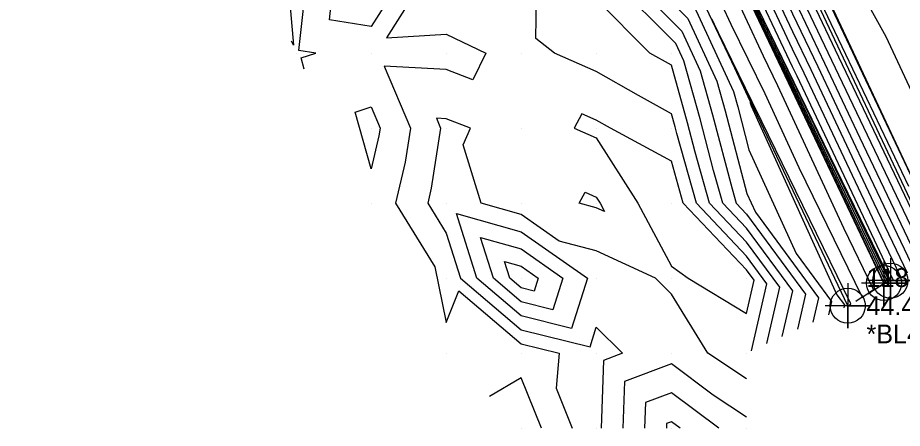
# Model space of a CAD drawing. Extents: x 2090860 to 2091277, y 159470 to 160080.
# Drawn here: x 2091052.9 to 2091170.8, y 159470 to 159524.7 of the extents above; entities that cross this region are included whole.
import ezdxf

# ---------------------------------------------------------------- set-up
doc = ezdxf.new("R2010")
doc.units = 0
for name, color, linetype in [('DTM Contours Major', 7, 'Continuous'), ('DTM Contours Minor', 7, 'Continuous'), ('Exist DTM Breakline', 7, 'Continuous'), ('Exist DTM Breakline Cogo Comment', 7, 'Continuous'), ('Exist DTM Breakline Cogo Elevation', 7, 'Continuous'), ('Exist DTM Breakline Cogo Number', 7, 'Continuous'), ('Exist DTM Breakline Cogo Point CELL', 7, 'Continuous'), ('Exist DTM QL2 LIDAR Elevation Point', 7, 'Continuous'), ('Exist Roads EOP', 7, 'Continuous')]:
    doc.layers.add(name, color=color, linetype=linetype)

msp = doc.modelspace()

# ---------------------------------------------------------------- linework, layer by layer
at = {"layer": 'DTM Contours Major'}
for points in [[(2091123.21, 159594.52), (2091129.91, 159580.68), (2091136.47, 159567.62), (2091138.12, 159564.05), (2091140.2, 159559.58), (2091146.27, 159546.39), (2091152.79, 159532.35), (2091156.16, 159525.23), (2091159.5, 159518.23), (2091166.04, 159504.37), (2091172.36, 159491.13)], [(2091128.34, 159593.56), (2091139.93, 159569.54), (2091140.97, 159567.34), (2091143.92, 159560.98), (2091147.21, 159553.98), (2091156.59, 159533.79), (2091161.27, 159523.96), (2091163.21, 159519.86), (2091171.58, 159502.29)], [(2091107.49, 159593.3), (2091109.23, 159589.68), (2091112.12, 159585.33), (2091119.2, 159570.67), (2091114.92, 159567.89), (2091120.85, 159560.32), (2091121.4, 159559.35), (2091126.5, 159553), (2091130.34, 159546.45), (2091137.49, 159533.43), (2091138.02, 159528.79), (2091142.19, 159524.62), (2091146.07, 159516.26), (2091147.17, 159512.31), (2091150.06, 159501.29), (2091151.2, 159498.79), (2091159.61, 159487.39), (2091158.87, 159484.16)], [(2091119.62, 159592.62), (2091130.86, 159569.9), (2091132.95, 159565.75), (2091135.92, 159559.3), (2091136.42, 159558.22), (2091136.43, 159558.2), (2091136.46, 159558.15), (2091149.11, 159531.02), (2091149.46, 159530.28), (2091156.03, 159516.65), (2091157.29, 159514), (2091169.04, 159489.62), (2091168.66, 159489.37)], [(2091165.38, 159487.43), (2091166.95, 159488.49), (2091162.97, 159496.65), (2091154.19, 159515.65), (2091152.26, 159519.58), (2091147.4, 159530.11), (2091145.52, 159535.03), (2091136.24, 159557.07), (2091135.82, 159557.96), (2091132.52, 159565.03), (2091132.34, 159565.41), (2091129.86, 159570.34), (2091117.8, 159591.64)], [(2091091.07, 159517.86), (2091090.65, 159519.35), (2091092.62, 159520), (2091090.36, 159520.36), (2091091.43, 159530), (2091090, 159532.48), (2091088.61, 159532.78), (2091089.65, 159521.06), (2091089.36, 159521.61)], [(2091107.07, 159530), (2091102.04, 159522.04), (2091110, 159522.53), (2091115.27, 159520), (2091113.55, 159516.45), (2091110, 159517.81), (2091101.75, 159518.25), (2091105.22, 159510), (2091104.52, 159505.48), (2091103.23, 159500), (2091108.46, 159491.54), (2091110, 159484.12), (2091111.68, 159488.32), (2091120, 159481.26), (2091125.06, 159480), (2091124.64, 159475.36), (2091126.8, 159470)], [(2091150.68, 159480.32), (2091152.74, 159489.26), (2091150, 159492.96), (2091143.34, 159500), (2091140.72, 159509.28), (2091140.49, 159510.16), (2091140, 159511.9), (2091135.63, 159514.37), (2091130, 159517.55), (2091124.42, 159520), (2091121.95, 159521.95), (2091122.09, 159530)], [(2091127.71, 159500), (2091128.53, 159501.47), (2091130, 159500.82), (2091130.52, 159500), (2091131.11, 159498.89), (2091130, 159499.4), (2091127.71, 159500)], [(2091120, 159488.71), (2091118.48, 159490), (2091117.78, 159492.22), (2091120, 159491.6), (2091122.27, 159490), (2091121.72, 159488.28), (2091120, 159488.71)], [(2091141.17, 159470), (2091140, 159470.88), (2091139.36, 159470.64), (2091139.34, 159470)]]:
    msp.add_lwpolyline(points, dxfattribs=at)
at = {"layer": 'DTM Contours Minor'}
for points in [[(2091131.42, 159598.52), (2091140.27, 159579.96), (2091144.16, 159571.35), (2091147, 159565.67), (2091150.37, 159558.45), (2091159.04, 159541.04), (2091163.85, 159530.74), (2091168.57, 159522.2), (2091174.47, 159509.57)], [(2091127.82, 159597.21), (2091138.56, 159574.44), (2091140.64, 159570.11), (2091144.22, 159562.5), (2091144.73, 159561.4), (2091156.04, 159537.32), (2091157.47, 159534.24), (2091158.19, 159532.74), (2091164.14, 159520.13), (2091165.09, 159518.14), (2091176.96, 159492.99)], [(2091126.02, 159596), (2091138.04, 159571.18), (2091139.12, 159569.03), (2091139.39, 159568.44), (2091143.03, 159560.61), (2091144.03, 159558.44), (2091155.66, 159533.4), (2091156.21, 159532.23), (2091162.28, 159519.5), (2091163.24, 159517.46), (2091175.19, 159492.42)], [(2091124.14, 159595.01), (2091132.62, 159577.51), (2091137.36, 159568.09), (2091138.54, 159565.51), (2091141.14, 159559.92), (2091145.52, 159550.4), (2091153.75, 159532.7), (2091156.17, 159527.57), (2091160.42, 159518.66), (2091165.11, 159508.73), (2091173.3, 159491.56)], [(2091125.08, 159595.51), (2091135.33, 159574.35), (2091138.24, 159568.56), (2091138.97, 159566.98), (2091142.08, 159560.26), (2091144.77, 159554.42), (2091154.7, 159533.05), (2091156.19, 159529.9), (2091161.35, 159519.08), (2091164.18, 159513.1), (2091174.25, 159491.99)], [(2091108.66, 159593.82), (2091110.67, 159589.63), (2091112.65, 159586.66), (2091121.5, 159568.34), (2091118.46, 159566.36), (2091122.67, 159560.99), (2091124.41, 159557.95), (2091127.88, 159553.64), (2091130.49, 159549.18), (2091140.66, 159530.65), (2091140.93, 159528.36), (2091142.99, 159526.29), (2091148.27, 159514.9), (2091148.85, 159512.85), (2091150.34, 159507.13), (2091156.63, 159493.3), (2091161.33, 159486.92), (2091160.92, 159485.12)], [(2091121.34, 159593.53), (2091124.5, 159587.01), (2091134.71, 159566.68), (2091137.27, 159561.12), (2091138.31, 159558.89), (2091147.77, 159538.35), (2091150.88, 159531.66), (2091156.12, 159520.56), (2091157.64, 159517.38), (2091167.91, 159495.64), (2091170.47, 159490.27), (2091170.45, 159490.22)], [(2091122.27, 159594.02), (2091127.2, 159583.84), (2091135.59, 159567.15), (2091137.7, 159562.59), (2091139.25, 159559.23), (2091147.02, 159542.37), (2091151.83, 159532.01), (2091156.14, 159522.9), (2091158.57, 159517.81), (2091166.98, 159500), (2091171.42, 159490.7)], [(2091106.31, 159592.78), (2091107.78, 159589.73), (2091111.59, 159584), (2091116.9, 159573), (2091111.38, 159569.41), (2091114.22, 159565.78), (2091116.48, 159560), (2091120, 159558.75), (2091125.12, 159552.37), (2091130.2, 159543.71), (2091134.31, 159536.22), (2091135.12, 159529.23), (2091141.39, 159522.94), (2091143.86, 159517.62), (2091145.5, 159511.77), (2091148.09, 159501.91), (2091148.63, 159500), (2091150, 159498.55), (2091157.89, 159487.86), (2091156.82, 159483.2)], [(2091119.2, 159592.39), (2091123.93, 159582.84), (2091132.63, 159565.57), (2091134.47, 159561.63), (2091136.12, 159558.08), (2091143.73, 159541.81), (2091148.81, 159530.9), (2091153.14, 159521.79), (2091155.67, 159516.52), (2091164.42, 159498.08), (2091168.58, 159489.45), (2091167.02, 159488.4)], [(2091119.41, 159592.5), (2091128.51, 159574.11), (2091132.78, 159565.65), (2091135.45, 159559.92), (2091136.28, 159558.14), (2091140.09, 159549.98), (2091148.96, 159530.96), (2091151.3, 159526.03), (2091155.85, 159516.59), (2091160.85, 159506.04), (2091168.81, 159489.54), (2091167.84, 159488.89)], [(2091120.4, 159593.03), (2091121.79, 159590.17), (2091133.83, 159566.21), (2091136.85, 159559.66), (2091137.37, 159558.55), (2091148.52, 159534.34), (2091149.92, 159531.31), (2091156.11, 159518.23), (2091156.71, 159516.96), (2091168.84, 159491.27), (2091169.53, 159489.84), (2091169.52, 159489.83)], [(2091164.56, 159486.95), (2091165.44, 159487.54), (2091157.04, 159504.73), (2091152.48, 159514.58), (2091147.96, 159523.81), (2091145.56, 159529.01), (2091140.8, 159541.42), (2091134.23, 159557.02), (2091133.33, 159559.3), (2091131.04, 159564.72), (2091127.32, 159571.89), (2091116.53, 159590.97)], [(2091166.2, 159487.92), (2091168.35, 159489.36), (2091167.98, 159490.11), (2091155.5, 159516.46), (2091154.97, 159517.54), (2091148.66, 159530.85), (2091147.36, 159533.64), (2091135.97, 159558.02), (2091133.49, 159563.33), (2091132.49, 159565.49), (2091119.34, 159591.57)], [(2091104.09, 159530), (2091100, 159523.53), (2091094.43, 159524.43), (2091095.04, 159530)], [(2091154.78, 159482.24), (2091156.17, 159488.32), (2091150, 159496.69), (2091146.87, 159500), (2091145.63, 159504.37), (2091143.83, 159511.24), (2091141.66, 159518.98), (2091140.6, 159521.26), (2091132.22, 159529.67)], [(2091152.73, 159481.28), (2091154.46, 159488.79), (2091150, 159494.82), (2091145.1, 159500), (2091143.18, 159506.82), (2091142.16, 159510.7), (2091140, 159518.39), (2091137.15, 159520), (2091130, 159527.24)], [(2091163.73, 159486.46), (2091163.92, 159486.59), (2091151.11, 159512.81), (2091150.78, 159513.52), (2091145.39, 159524.51), (2091150.48, 159513.54), (2091150.52, 159513.39), (2091150.62, 159512.98), (2091162.06, 159487.8), (2091163.05, 159486.46), (2091162.97, 159486.07)], [(2091100, 159504.59), (2091097.87, 159512.13), (2091100, 159512.83), (2091101.19, 159510), (2091101.03, 159508.97), (2091100, 159504.59)], [(2091150, 159476.59), (2091144.88, 159480), (2091140, 159487.89), (2091137.89, 159490), (2091130, 159493.66), (2091125.05, 159494.95), (2091120, 159498.5), (2091114.67, 159500), (2091112.24, 159507.76), (2091113.23, 159510), (2091110, 159511.24), (2091108.69, 159511.31), (2091109.24, 159510), (2091108.01, 159501.99), (2091107.54, 159500), (2091110, 159496.02), (2091111.89, 159490), (2091120, 159483.12), (2091129.16, 159480.84), (2091130, 159483.47), (2091133.47, 159480), (2091130.95, 159479.05), (2091130.63, 159470)], [(2091151.02, 159489.72), (2091150, 159491.1), (2091141.58, 159500), (2091140, 159505.6), (2091131.9, 159510), (2091130, 159511.07), (2091128.09, 159511.91), (2091127.04, 159510), (2091130, 159508.7), (2091135.51, 159500), (2091140, 159491.59), (2091142.23, 159490), (2091150, 159485.31), (2091151.02, 159489.72)], [(2091120, 159484.99), (2091114.09, 159490), (2091111.37, 159498.63), (2091120, 159496.2), (2091128.81, 159490), (2091126.68, 159483.32), (2091120, 159484.99)], [(2091120, 159486.85), (2091116.28, 159490), (2091114.57, 159495.43), (2091120, 159493.9), (2091125.54, 159490), (2091124.2, 159485.8), (2091120, 159486.85)], [(2091150, 159471.48), (2091145.58, 159474.42), (2091140, 159478.59), (2091133.75, 159476.25), (2091133.53, 159470)], [(2091122.71, 159470), (2091120, 159476.74), (2091115.77, 159474.23)], [(2091146.33, 159470), (2091140, 159474.73), (2091136.56, 159473.44), (2091136.44, 159470)]]:
    msp.add_lwpolyline(points, dxfattribs=at)
at = {"layer": 'Exist DTM Breakline'}
for points in [[(2091168.33, 159489.35), (2091148.61, 159530.83), (2091132.31, 159565.39), (2091116.34, 159597.57), (2091098.7, 159637.59), (2091084.7, 159667.25), (2091067.16, 159699.24), (2091053.41, 159724.44), (2091052.89, 159730.3), (2091057.39, 159734.95)], [(2091169.18, 159489.68), (2091149.14, 159531.03), (2091132.91, 159565.73), (2091117.09, 159597.89), (2091099.25, 159637.73), (2091085.44, 159667.51), (2091069.3, 159700.06), (2091060.28, 159722.82), (2091058.46, 159734.2), (2091059.36, 159735), (2091060.62, 159735.81)], [(2091175.56, 159492.59), (2091156.22, 159533.6), (2091139.64, 159569.31), (2091124.33, 159601.66), (2091105.94, 159640.92), (2091091.73, 159670.47), (2091076.45, 159703.52), (2091059.36, 159735)], [(2091163.51, 159486.33), (2091143.76, 159527.93), (2091127.12, 159562.65), (2091111.11, 159594.9), (2091093.03, 159634.87), (2091078.89, 159664.39)]]:
    msp.add_lwpolyline(points, dxfattribs=at)
at = {"layer": 'Exist DTM Breakline Cogo Point CELL'}
for points in [[(2091168.33, 159492.35), (2091168.33, 159486.35), (2091168.33, 159489.35), (2091171.33, 159489.35), (2091165.33, 159489.35)], [(2091169.18, 159492.68), (2091169.18, 159486.68), (2091169.18, 159489.68), (2091172.18, 159489.68), (2091166.18, 159489.68)], [(2091163.51, 159489.33), (2091163.51, 159483.33), (2091163.51, 159486.33), (2091166.51, 159486.33), (2091160.51, 159486.33)]]:
    msp.add_lwpolyline(points, dxfattribs=at)
for centre in [(2091169.18, 159489.68), (2091168.33, 159489.35), (2091163.51, 159486.33)]:
    msp.add_circle(centre, 2.34, dxfattribs=at)
at = {"layer": 'Exist DTM QL2 LIDAR Elevation Point'}
for p, q in [((2091090, 159520), (2091090, 159520)), ((2091100, 159520), (2091100, 159520)), ((2091110, 159520), (2091110, 159520)), ((2091120, 159520), (2091120, 159520)), ((2091130, 159520), (2091130, 159520)), ((2091140, 159520), (2091140, 159520)), ((2091100, 159510), (2091100, 159510)), ((2091110, 159510), (2091110, 159510)), ((2091120, 159510), (2091120, 159510)), ((2091130, 159510), (2091130, 159510)), ((2091140, 159510), (2091140, 159510)), ((2091100, 159500), (2091100, 159500)), ((2091110, 159500), (2091110, 159500)), ((2091120, 159500), (2091120, 159500)), ((2091130, 159500), (2091130, 159500)), ((2091140, 159500), (2091140, 159500)), ((2091150, 159500), (2091150, 159500)), ((2091110, 159490), (2091110, 159490)), ((2091120, 159490), (2091120, 159490)), ((2091130, 159490), (2091130, 159490)), ((2091140, 159490), (2091140, 159490)), ((2091150, 159490), (2091150, 159490)), ((2091110, 159480), (2091110, 159480)), ((2091120, 159480), (2091120, 159480)), ((2091130, 159480), (2091130, 159480)), ((2091140, 159480), (2091140, 159480)), ((2091150, 159480), (2091150, 159480)), ((2091120, 159470), (2091120, 159470)), ((2091130, 159470), (2091130, 159470)), ((2091140, 159470), (2091140, 159470)), ((2091150, 159470), (2091150, 159470))]:
    msp.add_line(p, q, dxfattribs=at)
at = {"layer": 'Exist Roads EOP'}
msp.add_lwpolyline([(2091176.99, 159493), (2091157.63, 159534.32), (2091140.8, 159570.23), (2091125.68, 159602.45), (2091107.65, 159641.5), (2091093.37, 159671.64), (2091078.49, 159704.36), (2091063.61, 159736.87)], dxfattribs=at)

# ---------------------------------------------------------------- texts
at = {"layer": 'Exist DTM Breakline Cogo Comment'}
msp.add_text('*BL40058', height=2.5, dxfattribs=at).set_placement((2091166.01, 159481.33))
at = {"layer": 'Exist DTM Breakline Cogo Elevation'}
msp.add_text('44.43', height=2.5, dxfattribs=at).set_placement((2091166.01, 159485.08))
at = {"layer": 'Exist DTM Breakline Cogo Number'}
msp.add_text('118', height=2.5, dxfattribs=at).set_placement((2091166.01, 159488.83))

doc.saveas('drawing.dxf')
